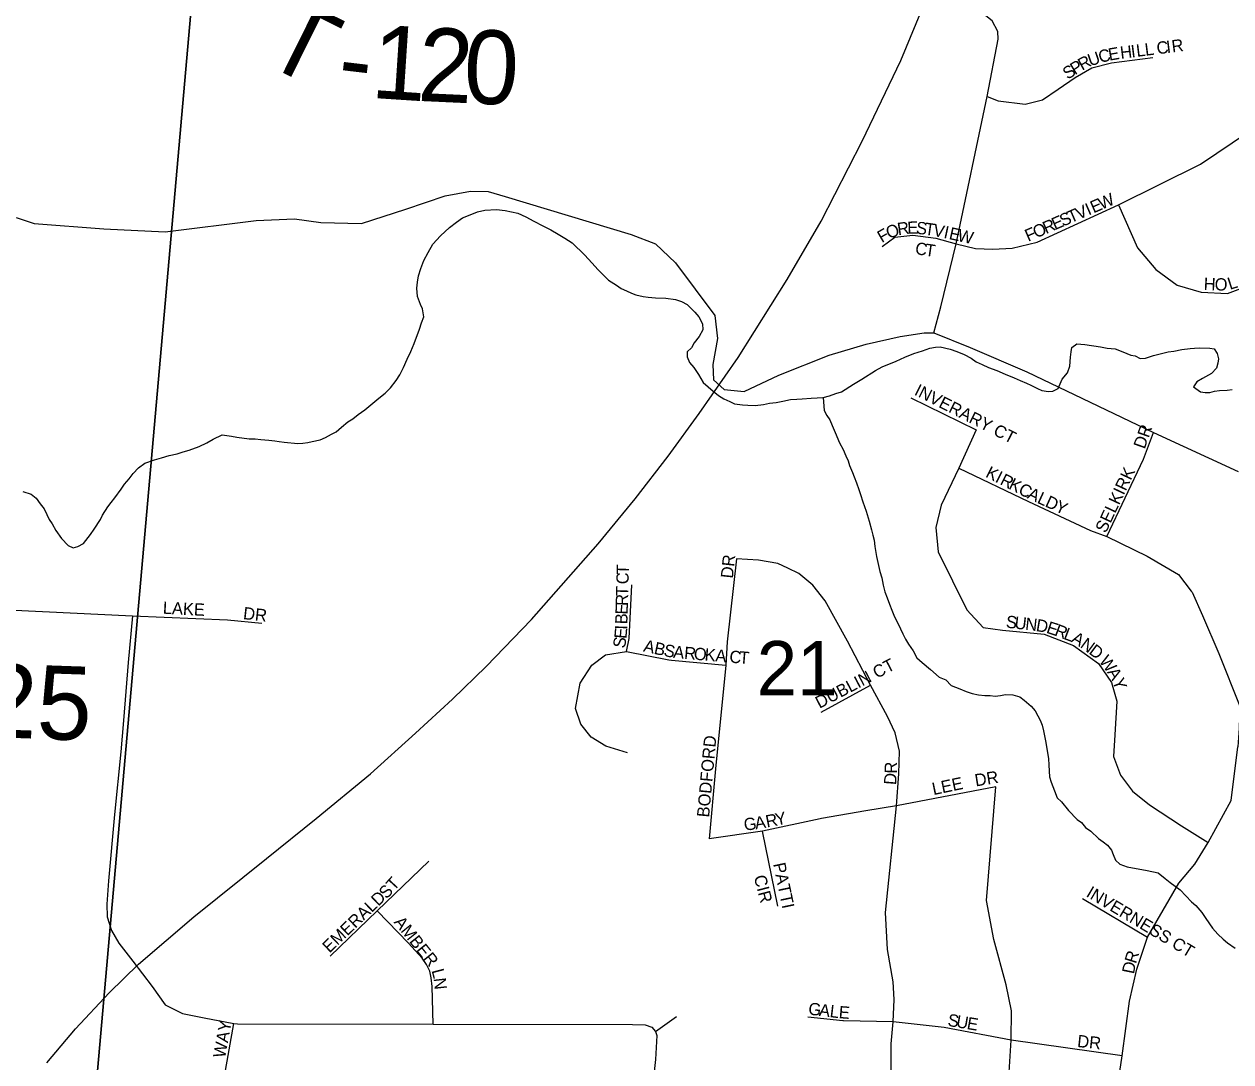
# Model space of a CAD drawing. Extents: x 1310247 to 1552180, y 377264 to 706493.
# Drawn here: x 1428558 to 1433472, y 484836 to 489060 of the extents above; entities that cross this region are included whole.
import ezdxf

# ---------------------------------------------------------------- set-up
doc = ezdxf.new("R2010")
doc.units = 0
for name, color, linetype in [('GM_X_Minor_River', 7, 'Continuous'), ('GM_X_Rail_Line', 7, 'Continuous'), ('GM_X_Section', 7, 'Continuous'), ('GM_X_Section_Text', 7, 'Continuous'), ('GM_X_Township_Road', 7, 'Continuous'), ('GM_X_Township_Road_Text', 7, 'Continuous'), ('GM_X_Township_Subdivision', 7, 'Continuous'), ('GM_X_Township_Subdivision_Text', 7, 'Continuous')]:
    doc.layers.add(name, color=color, linetype=linetype)

msp = doc.modelspace()

# ---------------------------------------------------------------- linework, layer by layer
at = {"layer": 'GM_X_Minor_River'}
for points in [[(1430172.6, 488066), (1430185.6, 488097.8), (1430202.6, 488131.4), (1430221.7, 488164.9), (1430252.8, 488198.1), (1430289.9, 488233.1), (1430318.6, 488254.3), (1430343.2, 488271.6), (1430373.7, 488284.7), (1430404.1, 488295.8), (1430434.4, 488302.9), (1430480.7, 488305.5), (1430516.7, 488302.4), (1430568.5, 488290.8), (1430600.2, 488275.8), (1430633.8, 488258.7), (1430669.4, 488239.5), (1430703, 488222.5), (1430732.6, 488205.5), (1430760.2, 488188.6), (1430789.8, 488169.6), (1430840.5, 488119.9), (1430869.7, 488088.9), (1430894.9, 488060), (1430914.4, 488041.4), (1430937.9, 488018.6), (1430969.3, 487997.5), (1430989, 487984.9), (1431010.8, 487974.2), (1431030.6, 487965.6), (1431048.5, 487959), (1431078.4, 487952.1), (1431098.4, 487949.4), (1431128.4, 487946.5), (1431170.5, 487945.2), (1431210.5, 487940), (1431234.3, 487931.2), (1431258, 487918.5), (1431289.2, 487887.4), (1431304.7, 487868.9), (1431319.9, 487840.3), (1431321.3, 487816.2), (1431306.4, 487788.5), (1431285.6, 487763.1), (1431275, 487743.3), (1431258.4, 487725.8), (1431257.8, 487705.7), (1431267.2, 487683.3), (1431284.6, 487662.8), (1431303.9, 487634.1), (1431323, 487601.4), (1431364.1, 487566), (1431385.7, 487549.3), (1431407.3, 487534.6), (1431431.1, 487523.8), (1431450.9, 487515.1), (1431482.9, 487510.2), (1431504.9, 487509.5), (1431535, 487508.6), (1431569.2, 487511.5), (1431593.4, 487516.8), (1431619.6, 487520), (1431647.9, 487525.2), (1431678.2, 487532.3), (1431704.3, 487533.5), (1431726.4, 487534.8), (1431762.6, 487537.8), (1431810.9, 487540.3), (1431837.2, 487547.5), (1431863.5, 487556.7), (1431885.8, 487564.1), (1431934.9, 487594.7), (1431969.6, 487615.7), (1432024.8, 487650.2), (1432051.3, 487665.4), (1432108.2, 487687.8), (1432144.8, 487704.7), (1432181.3, 487719.6), (1432215.8, 487730.6), (1432246.2, 487741.8), (1432268.4, 487745.1), (1432288.5, 487746.5), (1432328.4, 487737.2), (1432356.2, 487728.4), (1432385.9, 487715.4), (1432413.6, 487700.5), (1432435.2, 487685.8), (1432459, 487675), (1432484.7, 487662.2), (1432518.5, 487651.1), (1432552.2, 487636.1), (1432589.9, 487620.9), (1432613.6, 487610.1), (1432639.4, 487599.3), (1432657.2, 487590.7), (1432684.9, 487577.8), (1432702.7, 487569.2), (1432728.7, 487564.4), (1432746.8, 487565.9), (1432769.2, 487577.2), (1432784.4, 487614.9)], [(1428552.6, 487158.1), (1428586.4, 487147), (1428606, 487130.4), (1428623.4, 487107.8), (1428638.9, 487087.2), (1428650.3, 487064.8), (1428659.7, 487044.5), (1428671.2, 487026), (1428686.5, 486999.5), (1428709.6, 486966.7), (1428736.8, 486937.7), (1428756.7, 486929.1), (1428776.9, 486934.5), (1428799.3, 486945.8), (1428828.5, 486983.1), (1428843.2, 487004.7), (1428868.4, 487044.1), (1428876.9, 487061.9), (1428898, 487095.4), (1428912.6, 487113), (1428927.2, 487132.6), (1428952.3, 487168), (1428966.9, 487187.6), (1428985.6, 487209.1), (1429002.3, 487230.7), (1429023, 487254.1), (1429049.7, 487273.4), (1429088.2, 487286.3), (1429116.6, 487295.5), (1429148.9, 487304.5), (1429181.3, 487311.5), (1429205.6, 487318.8), (1429229.8, 487326.1), (1429270.4, 487340.9), (1429301, 487356), (1429327.5, 487371.3), (1429364.1, 487388.2), (1429402.1, 487383.1), (1429424, 487378.4), (1429474, 487372.8), (1429498.1, 487372.1), (1429522.1, 487369.4), (1429554.1, 487366.4), (1429578.1, 487363.6), (1429596.1, 487361.1), (1429616.1, 487358.5), (1429672.1, 487352.7), (1429692.2, 487354.1), (1429712.4, 487357.5), (1429730.6, 487361), (1429762.9, 487368), (1429785.2, 487377.4), (1429809.7, 487390.7), (1429828, 487400.2), (1429850.7, 487419.5), (1429875.4, 487440.9), (1429895.8, 487454.3), (1429918.4, 487471.7), (1429945.1, 487490.9), (1430002.6, 487537.3), (1430027.3, 487558.7), (1430050, 487580), (1430073, 487609.5), (1430087.7, 487633.1), (1430102.6, 487662.7), (1430117.7, 487696.4), (1430132.6, 487728.1), (1430145.6, 487759.8), (1430167.4, 487819.3), (1430176.2, 487845.1), (1430184.9, 487869), (1430179.9, 487901.2), (1430172.4, 487919.5), (1430159.3, 487952), (1430156.3, 487986.2), (1430159, 488010.3), (1430163.7, 488036.2), (1430172.6, 488066)], [(1432784.4, 487614.9), (1432807.2, 487640.3), (1432816, 487668.1), (1432819.1, 487704.2), (1432821.7, 487726.2), (1432824.3, 487744.2), (1432844.8, 487759.6), (1432876.8, 487756.6), (1432940.7, 487746.6), (1432968.7, 487741.8), (1433000.7, 487738.8), (1433032.4, 487725.8), (1433064.1, 487712.7), (1433082.1, 487710.2), (1433101.9, 487699.5), (1433124, 487700.9), (1433156.4, 487711.9), (1433194.8, 487720.8), (1433217.1, 487726.1), (1433239.2, 487729.5), (1433271.6, 487736.5), (1433305.8, 487739.5), (1433323.9, 487740.9), (1433346, 487742.3), (1433386.1, 487741), (1433404.1, 487738.5), (1433415.6, 487720.1), (1433420.9, 487697.8), (1433418.4, 487679.8), (1433413.8, 487659.9), (1433393.1, 487638.5), (1433356.4, 487617.5), (1433333.9, 487604.1), (1433319.3, 487584.5), (1433348.8, 487563.5), (1433366.8, 487561), (1433386.8, 487560.4), (1433405, 487565.8), (1433425.2, 487569.2), (1433457.3, 487570.3), (1433477.5, 487573.7)], [(1431810.9, 487540.3), (1431815.4, 487488), (1431826.8, 487467.5), (1431838.3, 487449.1), (1431847.7, 487426.8), (1431860.9, 487398.3), (1431877.7, 487355.6), (1431893, 487329), (1431904.2, 487302.6), (1431913.7, 487282.2), (1431919.2, 487264), (1431930.4, 487235.6), (1431937.9, 487217.3), (1431947.2, 487192.9), (1431956.5, 487166.5), (1431963.9, 487146.2), (1431973, 487115.8), (1431986, 487077.3), (1431998.8, 487036.8), (1432007.8, 487002.4), (1432013.2, 486980.1), (1432018.6, 486959.9), (1432021.9, 486933.7), (1432028.7, 486893.3), (1432043, 486832.7), (1432050.3, 486806.4), (1432055.4, 486776.1), (1432062.7, 486749.8), (1432072, 486725.4), (1432081.3, 486699), (1432090.6, 486674.7), (1432101.8, 486648.2), (1432115.1, 486621.7), (1432126.5, 486599.3), (1432135.9, 486579), (1432147.3, 486556.5), (1432158.8, 486536.1), (1432178.1, 486509.4), (1432193.3, 486480.9), (1432214.8, 486462.1), (1432248.1, 486433), (1432283.3, 486401.8), (1432311.1, 486390.9), (1432332.5, 486368.2), (1432368.2, 486355.1), (1432394, 486344.2), (1432417.8, 486335.5), (1432443.8, 486330.7), (1432469.8, 486327.9), (1432491.8, 486327.2), (1432511.8, 486324.6), (1432534, 486327.9), (1432554.2, 486331.3), (1432584.2, 486330.4), (1432612.1, 486321.5), (1432629.8, 486308.9), (1432659.1, 486284), (1432674.6, 486265.4), (1432686.1, 486245), (1432695.6, 486226.6), (1432703, 486206.3), (1432708.4, 486184.1), (1432719, 486135.6), (1432729.1, 486069.1), (1432730.4, 486044.9), (1432731.7, 486018.8), (1432733, 485996.7), (1432740.4, 485974.4), (1432753.4, 485939.8), (1432764.6, 485911.4), (1432782.2, 485894.8), (1432811.3, 485859.8), (1432846.3, 485822.6), (1432864, 485810), (1432879.5, 485789.5), (1432901.1, 485774.8), (1432932.4, 485745.7), (1432952, 485731.1), (1432969.7, 485718.5), (1432985.2, 485697.9), (1432992.7, 485679.6), (1433002.1, 485657.3), (1433019.6, 485640.7), (1433049.4, 485629.7), (1433131.3, 485615.2), (1433175.2, 485605.8), (1433204.6, 485582.8), (1433224.2, 485566.2), (1433265.5, 485536.8), (1433312.2, 485487.2), (1433329.8, 485472.6), (1433353.1, 485443.8), (1433370.4, 485419.2), (1433397.4, 485380.2), (1433418.7, 485355.5), (1433440.2, 485334.8), (1433457.8, 485320.2), (1433489.3, 485299.1)]]:
    msp.add_lwpolyline(points, dxfattribs=at)
at = {"layer": 'GM_X_Rail_Line'}
msp.add_lwpolyline([(1428649.7, 484831.5), (1428766.4, 484970), (1428903.9, 485116.8), (1429023.9, 485233.5), (1429249, 485426.9), (1429544.4, 485663.2), (1429746.5, 485826.5), (1429968, 486008.3), (1430151.7, 486173.5), (1430302.1, 486312), (1430438.7, 486444.9), (1430623.3, 486636.9), (1430895.6, 486945.1), (1431046, 487127.9), (1431180.7, 487301.4), (1431307.2, 487474.9), (1431465, 487703.8), (1431664.4, 488020.3), (1431803.7, 488258.4), (1431970.8, 488584.2), (1432127.7, 488911.9), (1432252.3, 489215.5)], dxfattribs=at)
at = {"layer": 'GM_X_Section'}
for points in [[(1423863.5, 489580.6), (1429255.8, 489324.6), (1428777.4, 483907.1), (1423391.5, 484184.8)], [(1434523.9, 489065.4), (1433994.3, 483685), (1428777.4, 483907.1), (1429255.8, 489324.6)]]:
    msp.add_lwpolyline(points, close=True, dxfattribs=at)
at = {"layer": 'GM_X_Township_Road'}
for points in [[(1432261.9, 487803.1), (1432291.4, 487909.7), (1432353.6, 488165.6), (1432478.8, 488765.2), (1432524.7, 488999.1), (1432522.4, 489030.8), (1432499.8, 489074.4), (1432460.7, 489105.6), (1432539.4, 489260.2), (1432592.1, 489340), (1432933, 489883.1), (1432984.5, 489987.3), (1433076.6, 490173.6), (1433132.5, 490354.6), (1433194.5, 490721.5)], [(1428525.1, 488273.1), (1428598, 488248.8), (1428881.6, 488226.9), (1429131.6, 488214.4), (1429503.1, 488261), (1429658, 488268.1), (1429765.4, 488252.3), (1429931.4, 488248.8), (1430111.6, 488307.6), (1430271.6, 488361.2), (1430374.8, 488380.5), (1430447.7, 488379.4), (1430516.4, 488358.5), (1431029.9, 488204.3), (1431129.1, 488165.8), (1431209.7, 488089.1), (1431370.9, 487873.9), (1431381.2, 487780.1), (1431362, 487674.8), (1431365, 487613), (1431408.6, 487572.5), (1431489.5, 487565.3), (1431631.3, 487631.2), (1431835.8, 487712.2), (1431986.7, 487757.8), (1432124.9, 487789.5), (1432222.3, 487804.2), (1432261.9, 487803.1), (1432409.7, 487744.7), (1432640.5, 487644.5), (1433156.7, 487398.1), (1433502.2, 487239)], [(1427793.6, 486697.1), (1428264.2, 486686.4), (1428998.9, 486652.1), (1428981, 486461.7), (1428962.6, 486225.5), (1428952, 486098.3), (1428925.1, 485842.9), (1428901.1, 485573.5), (1428893.9, 485477.4), (1428895.6, 485425.7), (1428913.9, 485370.2), (1428943.8, 485319.8), (1428999.8, 485246.4), (1429079.6, 485143), (1429132.6, 485067.9), (1429202.9, 485032.7), (1429291, 485015.8), (1429411.4, 484991.5), (1429426.1, 484991.4)], [(1429426.1, 484991.4), (1430223.6, 484989.7), (1431035.7, 484988), (1431086.6, 484986.1), (1431113.4, 484977.8), (1431129.2, 484959.3), (1431134.7, 484943.6), (1431128.2, 484845.5), (1431093.5, 484521.3), (1431050.5, 484110.7), (1431036.6, 483786.8), (1431930.4, 483759), (1432525.7, 483732.4), (1433313.7, 483704.9), (1433388, 483700.2), (1433815.7, 483679.2), (1434006.9, 483666.3), (1434168.3, 483614.6), (1434238.2, 483598.8), (1435803.9, 483188.9), (1435814.4, 483186.1), (1436629.6, 482989.6)]]:
    msp.add_lwpolyline(points, dxfattribs=at)
at = {"layer": 'GM_X_Township_Subdivision'}
for points in [[(1432478.8, 488765.2), (1432523.6, 488748.8), (1432634, 488735.2), (1432704.2, 488752.8), (1432768.2, 488795.8), (1432837.3, 488843.4), (1432905.2, 488883), (1432985.1, 488903.4), (1433154.4, 488924.9)], [(1432353.6, 488165.6), (1432431.8, 488146.8), (1432502.6, 488144.5), (1432580.8, 488149.1), (1432682.7, 488172.3), (1433014.6, 488325.2), (1433348.6, 488490.2), (1433544, 488621.5), (1433647.5, 488712.1), (1433724.6, 488768.8), (1433768.4, 488786.8), (1433811.8, 488796.5), (1433859.7, 488794.2), (1433916.5, 488781.2), (1433966.8, 488758.2), (1434012, 488725.9), (1434055.3, 488670.5), (1434084.5, 488589.8), (1434104.7, 488439.4), (1434120.9, 488336.1)], [(1433014.6, 488325.2), (1433091.6, 488150.3), (1433166.7, 488061.3), (1433252.6, 487997.9), (1433350.4, 487969.8), (1433458.1, 487964.4), (1433610.6, 488021), (1433742.8, 488115.7), (1433890.6, 488242.9), (1433974.6, 488288.6), (1434120.9, 488336.1), (1434224.2, 488342.1), (1434649.3, 488289), (1434914.3, 488271.5), (1434973.3, 488274.7), (1435049.5, 488299.6), (1435249, 488448.5), (1435341.5, 488500.3), (1435426.8, 488528), (1435512.2, 488538.6), (1435580.4, 488537.7), (1435679.6, 488518.3), (1435757.5, 488495.6)], [(1432051.8, 488155.9), (1432103.4, 488193.2), (1432176.4, 488201.2), (1432270.3, 488188.7), (1432353.6, 488165.6)], [(1432169, 487539.3), (1432435.1, 487408.8)], [(1432435.1, 487408.8), (1432364.4, 487253.1), (1432292, 487102.4), (1432270.6, 487010.8), (1432279.4, 486911.6), (1432396.2, 486676.8), (1432462.7, 486604), (1432541.8, 486594), (1432711, 486577.6), (1432830.6, 486531.2), (1432933.5, 486457.1), (1432986.2, 486380.6), (1433007.6, 486304), (1432998.8, 486167.1), (1432993.8, 486079.2), (1433022.7, 486002.7), (1433071.6, 485938.6), (1433140.7, 485882.1), (1433271.2, 485796.8), (1433379.2, 485729)], [(1432967, 486974.6), (1433115.9, 487290), (1433156.7, 487398.1)], [(1432364.4, 487253.1), (1432647.2, 487116.9), (1432899.8, 486999.3), (1432967, 486974.6), (1433130.6, 486894), (1433258.7, 486820), (1433310.7, 486752.6)], [(1431458.1, 486884.3), (1431420.9, 486545.4), (1431415, 486451.2), (1431372.6, 486028.4), (1431347.8, 485744.5)], [(1431668.3, 486845.1), (1431627.3, 486865), (1431548.2, 486877.8), (1431458.1, 486884.3)], [(1432083.3, 484690.5), (1432088.8, 484809), (1432088.4, 484909.4), (1432096.1, 484998.3), (1432100.7, 485089.8), (1432096.1, 485162.4), (1432073.1, 485293.9), (1432065.5, 485444.1), (1432110.2, 485877.8), (1432119.8, 486008.1), (1432122.8, 486100.1), (1432104.5, 486175.9), (1432073.8, 486242.4), (1432004.2, 486369.8), (1431910.4, 486548.7), (1431820.3, 486713.3), (1431769.7, 486776.7), (1431712.8, 486823.6), (1431668.3, 486845.1)], [(1431010.7, 486507), (1431021.4, 486559.2), (1431032.2, 486777.3)], [(1433310.7, 486752.6), (1433313.9, 486748.4), (1433356.6, 486653), (1433423.4, 486498.5), (1433508.5, 486283.9), (1433506, 486194.7), (1433499.7, 486118.2)], [(1428998.9, 486652.1), (1429385.4, 486635.6), (1429525.9, 486621.4)], [(1431015.3, 486093.7), (1430926.2, 486121.4), (1430866.3, 486158.3), (1430824.8, 486210.5), (1430803.3, 486274.8), (1430821.4, 486377.3), (1430869.8, 486451), (1430924.7, 486493.2), (1431010.7, 486507), (1431182.7, 486472), (1431193.7, 486471)], [(1431193.7, 486471), (1431415, 486451.2)], [(1431802.8, 486260.1), (1432004.2, 486369.8)], [(1433091.9, 485221.3), (1433131.8, 485344.2), (1433259.9, 485563.3), (1433325.2, 485641.1), (1433379.2, 485729), (1433473.3, 485899.7), (1433499.7, 486118.2)], [(1432514.4, 485955.8), (1432110.2, 485877.8), (1431985.8, 485858.3), (1431804.3, 485826.2)], [(1432525.7, 483732.4), (1432541.9, 484192.4), (1432542.5, 484200.4), (1432568.3, 484772.6), (1432577.7, 484924.7), (1432578.5, 485043.7), (1432556.4, 485149.4), (1432506.9, 485333.7), (1432476.5, 485493.4), (1432514.4, 485955.8)], [(1431804.3, 485826.2), (1431799.2, 485825.2), (1431565.1, 485775.3), (1431347.8, 485744.5)], [(1431627.1, 485470.1), (1431565.1, 485775.3)], [(1429804.3, 485266.9), (1429995.1, 485450.8), (1430205.3, 485653.5)], [(1432868.2, 485500.5), (1433131.8, 485344.2)], [(1430223.6, 484989.7), (1430218.8, 485142.6), (1430214.8, 485178.4), (1430209.4, 485204.9), (1430196.1, 485232.6), (1430178.6, 485258.3), (1430122.6, 485318.6), (1429995.1, 485450.8)], [(1432959.8, 484176.2), (1432971.2, 484469.8), (1433029.8, 484860.4), (1433059, 485083.7), (1433089.2, 485213), (1433091.9, 485221.3)], [(1429399.1, 483653.7), (1429412, 484055.4), (1429436.1, 484235), (1429430.5, 484360.8), (1429362, 484527.4), (1429354.7, 484634.8), (1429373.1, 484777.2), (1429411.4, 484991.5)], [(1431129.2, 484959.3), (1431214.3, 485021.3)], [(1431892, 485002.9), (1431749.3, 485018.1)], [(1433029.8, 484860.4), (1432577.7, 484924.7), (1432304.5, 484975.7), (1432096.1, 484998.3), (1431894.5, 485002.6), (1431892, 485002.9)]]:
    msp.add_lwpolyline(points, dxfattribs=at)

# ---------------------------------------------------------------- texts
at = {"layer": 'GM_X_Section_Text'}
msp.add_text('21', height=221, rotation=0, dxfattribs=at).set_placement((1431541.1, 486328.1))
at = {"layer": 'GM_X_Township_Road_Text'}
for s, rotation, p in [('T', 333.6046, (1429518.8, 488908.2)), ('1', 356.2852, (1429966.4, 488760.5)), ('2', 357.3682, (1430156.9, 488748.2)), ('0', 357.665, (1430343.2, 488739.6)), ('-', 353.2445, (1429826.7, 488776.6)), ('T-125', 358.0445, (1427781.5, 486179.7))]:
    msp.add_text(s, height=300, rotation=rotation, dxfattribs=at).set_placement(p)
at = {"layer": 'GM_X_Township_Subdivision_Text'}
for s, rotation, p in [('E', 9.8576, (1432976.9, 488911.3)), ('H', 7.144, (1433024, 488919)), ('I', 7.1223, (1433067.7, 488924.4)), ('L', 7.1216, (1433089.5, 488927.2)), ('L', 7.1292, (1433124.4, 488931.5)), ('C', 7.1341, (1433172.5, 488937.5)), ('I', 7.1223, (1433211.8, 488942.5)), ('R', 7.122, (1433233.6, 488945.2)), ('R', 28.4118, (1432866, 488870.1)), ('U', 18.6423, (1432898.8, 488888)), ('C', 14.2689, (1432939.5, 488901.8)), ('S', 33.0611, (1432807.4, 488833.1)), ('P', 31.348, (1432836.5, 488852.1)), ('I', 23.5135, (1432892.3, 488281)), ('E', 23.5089, (1432912.5, 488289.8)), ('W', 23.5033, (1432944.8, 488303.8)), ('E', 23.4964, (1432755.1, 488221.3)), ('S', 23.5091, (1432787.4, 488235.4)), ('T', 23.5089, (1432819.7, 488249.4)), ('V', 23.5042, (1432852, 488263.5)), ('F', 29.8228, (1432050.3, 488168.6)), ('O', 22.2012, (1432079.3, 488185.3)), ('R', 8.2864, (1432117, 488201.1)), ('E', 1.5437, (1432154.6, 488206.6)), ('S', 353.0986, (1432187.8, 488207.7)), ('T', 352.0244, (1432222.5, 488203.5)), ('V', 349.3374, (1432256.8, 488198.7)), ('I', 347.6442, (1432299.6, 488190.6)), ('E', 347.4682, (1432321.1, 488185.9)), ('F', 23.5089, (1432646.2, 488174)), ('O', 23.5042, (1432678.5, 488188)), ('R', 23.5167, (1432718.8, 488205.5)), ('W', 347.4763, (1432355.5, 488178.3)), ('C', 350.0666, (1432183.4, 488125.1)), ('T', 351.4949, (1432223.8, 488118)), ('H', 357.2124, (1433360.5, 487978.9)), ('O', 358.3939, (1433405.5, 487976.7)), ('L', 18.0329, (1433468, 487978.2)), ('INVERARY CT', 333.1596, (1432179, 487553.3)), ('DR', 70.5586, (1433120.7, 487328.1)), ('K', 332.8925, (1432469.4, 487218.9)), ('SELKIRK', 64.747, (1432962.6, 486985.7)), ('I', 332.8993, (1432508.6, 487198.9)), ('R', 332.8919, (1432528.2, 487188.8)), ('K', 332.8859, (1432563.4, 487170.8)), ('C', 332.987, (1432602.7, 487150.7)), ('A', 334.5937, (1432639.3, 487132)), ('L', 335.3856, (1432679.7, 487112.9)), ('D', 335.4407, (1432711.8, 487098.2)), ('Y', 335.4439, (1432751.8, 487079.9)), ('T', 88.3607, (1431019.9, 486819.2)), ('DR', 83.994, (1431443.8, 486802.3)), ('C', 88.3665, (1431018.8, 486779.6)), ('T', 88.3607, (1431017.4, 486731.2)), ('LAKE', 356.9047, (1429121.6, 486660.5)), ('R', 88.3546, (1431016.3, 486691.7)), ('DR', 353.6571, (1429447.7, 486638.5)), ('B', 88.3665, (1431014.2, 486616.9)), ('E', 88.3607, (1431015.3, 486656.5)), ('I', 88.2551, (1431013.5, 486594.8)), ('S', 353.5391, (1432554.1, 486603.9)), ('U', 353.5391, (1432589.1, 486599.9)), ('N', 353.5391, (1432632.8, 486595)), ('D', 350.5485, (1432675.9, 486590.1)), ('E', 341.8156, (1432717.3, 486583.4)), ('R', 339.4951, (1432750.3, 486572.6)), ('S', 80.3782, (1431004, 486517.6)), ('E', 85.2976, (1431010.4, 486556.9)), ('L', 339.3097, (1432787.3, 486558.7)), ('A', 329.9772, (1432818.3, 486547.2)), ('N', 323.6175, (1432855.2, 486526)), ('A', 347.5648, (1431076.8, 486506.9)), ('B', 347.5766, (1431119.8, 486497.4)), ('S', 348.8644, (1431159.6, 486488.7)), ('A', 354.2426, (1431199.2, 486481.1)), ('R', 355.3123, (1431244, 486476.6)), ('O', 355.3082, (1431283.5, 486473.4)), ('K', 355.2954, (1431327.4, 486469.8)), ('A', 355.3023, (1431371.2, 486466.2)), ('C', 355.3005, (1431428.2, 486461.5)), ('D', 323.1804, (1432890.5, 486500)), ('T', 355.3099, (1431467.7, 486458.2)), ('DUBLIN CT', 27.6118, (1431796.3, 486272.9)), ('W', 307.117, (1432932.7, 486467.1)), ('A', 301.5467, (1432966.5, 486422.6)), ('Y', 290.4397, (1432988.4, 486387.4)), ('BODFORD', 84.8044, (1431346.9, 485829.7)), ('R', 88.9776, (1432111.8, 486009.1)), ('DR', 8.9738, (1432432.9, 485957)), ('D', 85.4714, (1432108.2, 485961.9)), ('LEE', 11.7672, (1432260.8, 485921.7)), ('G', 7.2321, (1431491.6, 485776.7)), ('A', 8.9195, (1431536.8, 485782.4)), ('R', 11.2449, (1431582.5, 485789.6)), ('Y', 11.3131, (1431621.4, 485797.4)), ('PATTI', 281.8878, (1431607.5, 485641.7)), ('ST', 47.4883, (1430033.8, 485496.5)), ('CIR', 284.6217, (1431528.6, 485589.6)), ('INVERNESS CT', 329.2366, (1432879.1, 485511.4)), ('EMERALD', 43.805, (1429801.1, 485277)), ('AMBER', 308.8021, (1430060.8, 485403.9)), ('R', 72.6902, (1433085.3, 485233.2)), ('D', 78.2807, (1433076.7, 485191.4)), ('L', 284.7088, (1430216.4, 485207.9)), ('N', 276.2412, (1430225, 485175.7)), ('G', 353.2193, (1431749.1, 485028.7)), ('A', 353.2203, (1431792.8, 485023.5)), ('L', 353.2231, (1431836.5, 485018.3)), ('E', 355.6268, (1431873.7, 485013.9)), ('WAY', 79.694, (1429375.9, 484849.4)), ('S', 351.1687, (1432316.3, 484982.7)), ('U', 350.3041, (1432350.9, 484977.3)), ('E', 350.2817, (1432394.3, 484969.9)), ('DR', 353.994, (1432844.5, 484896.7))]:
    msp.add_text(s, height=50, rotation=rotation, dxfattribs=at).set_placement(p)

doc.saveas('drawing.dxf')
